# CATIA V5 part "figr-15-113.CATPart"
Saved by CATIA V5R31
Part number: Part1
Bounding box of the stored display mesh (mm): x -55.37 to 68.649, y -21.457 to 35.984, z 0 to 57.441
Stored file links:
  D:\PROJECTS\Project 2021\US EDITION\CATIA V5 6R 2021\Resources\Part Files\c15_catia_v5_6r2021_prt\figr-15-113.CATPart
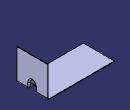
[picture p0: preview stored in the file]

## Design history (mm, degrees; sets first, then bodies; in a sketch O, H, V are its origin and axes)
SheetMetalParameters1: Thickness 1, BendRadius 2, KFactor 0.400515 {= log(min(100,max(20*SheetMetalParameters1.BendRadius,SheetMetalParameters1.Thickness)/SheetMetalParameters1.Thickness))/log(100)/2}, ReliefRadialLength 1, ReliefAxialLength 2, MinimumBendRadius 0
Body1 (main body)
  Sketch1 on xy-plane, origin (0, 0, 0), H (1, 0, 0), V (0, 1, 0)
    line L1 (-55.3695, 35.9836) -> (67.649, 35.9836)
    line L2 (67.649, 35.9836) -> (67.649, -21.4575)
    line L3 (67.649, -21.4575) -> (-55.3695, -21.4575)
    line L4 (-55.3695, -21.4575) -> (-55.3695, 35.9836)
    horizontal: L1 H, L3 H
    vertical: L2 V, L4 V
  Wall1: Thickness 1, Profile Sketch1
  d_NewWallOnEdge1: NewWallOnEdge_Edge edge [face of Wall1 | face of Wall1], NewWallOnEdge_Length 57.4411, NewWallOnEdge_HeightLimitOffset 0, NewWallOnEdge_WidthOffset1 0, NewWallOnEdge_WidthOffset2 0, NewWallOnEdge_Angle 90, NewWallOnEdge_BendRadiusValue 2 {= SheetMetalParameters1.BendRadius}, NewWallOnEdge_BendTable SheetMetalParameters1, KFacteur 0.400515 {= log(min(100,max(20*d_NewWallOnEdge1.Radius,SheetMetalParameters1.Thickness)/SheetMetalParameters1.Thickness))/log(100)/2}
  Sketch2 on , origin (67.7759, 6.9809, 0.8843), H (0.7052, 0, 0.709), V (0, -1, 0)
    point P1 (0, 0)
  d_Stamp1: Stamp_FilletRadius 2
